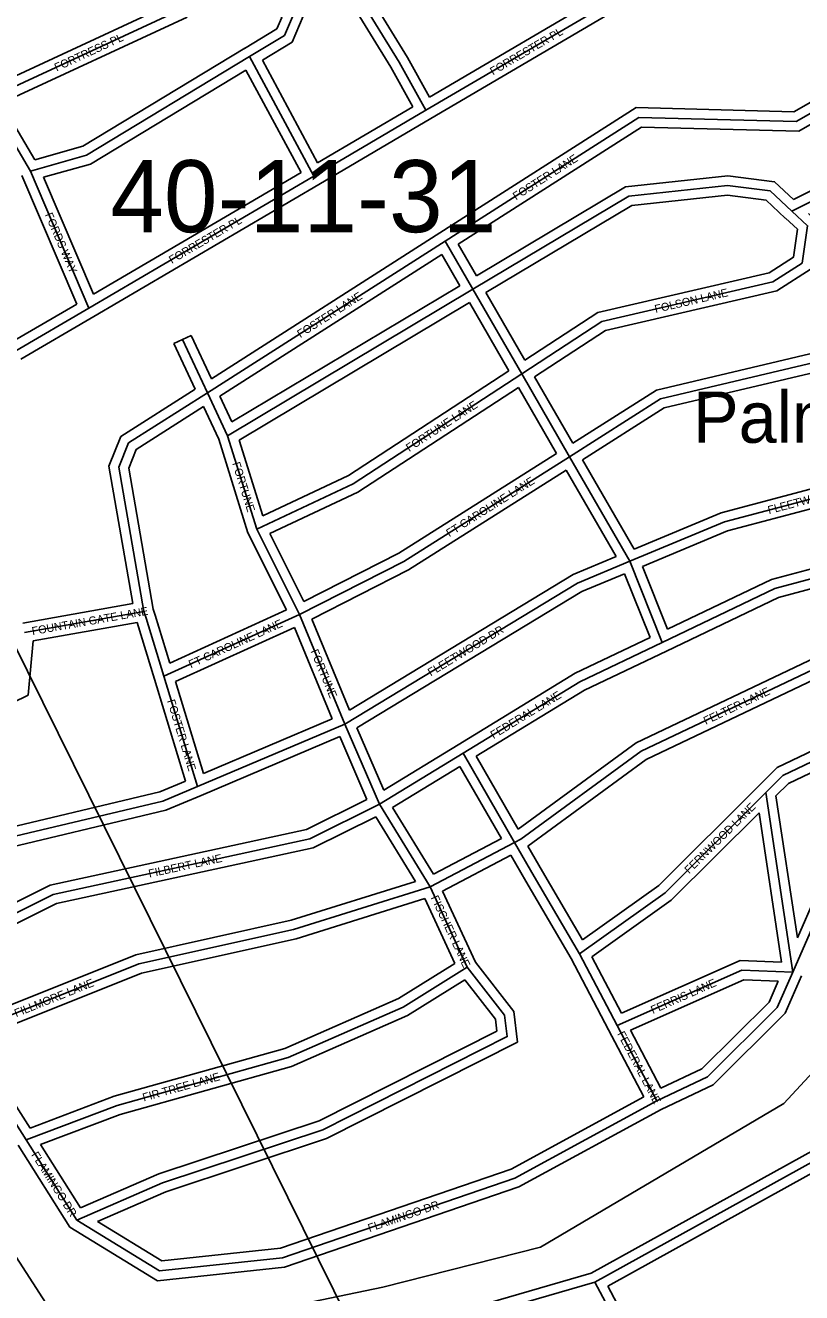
# Model space of a CAD drawing. Extents: x 457167 to 656239, y 1787309 to 1969297.
# Drawn here: x 586280 to 588703, y 1900964 to 1904923 of the extents above; entities that cross this region are included whole.
import ezdxf

# ---------------------------------------------------------------- set-up
doc = ezdxf.new("R2010")
doc.units = 0
for name, color, linetype in [('Level 1', 7, 'Continuous'), ('Level 2', 7, 'Continuous'), ('Level 31', 7, 'Continuous'), ('Level 32', 7, 'Continuous'), ('Level 34', 7, 'Continuous'), ('Level 44', 7, 'Continuous'), ('Level 5', 7, 'Continuous')]:
    doc.layers.add(name, color=color, linetype=linetype)

msp = doc.modelspace()

# ---------------------------------------------------------------- linework, layer by layer
at = {"layer": 'Level 1'}
msp.add_line((585103.985, 1905297.891), (587876.128, 1899689.718), dxfattribs=at)
at = {"layer": 'Level 31'}
for p, q in [((587446.958, 1904807.623), (587031.137, 1905483.681)), ((586163.078, 1904692.94), (586772.06, 1904975.432)), ((586980.002, 1904825.586), (587180.536, 1904452.115)), ((587446.958, 1904807.623), (587529.969, 1904657.65)), ((586163.078, 1904692.94), (586295.853, 1904467.958)), ((587529.969, 1904657.65), (587180.536, 1904452.115)), ((586295.853, 1904467.958), (586478.478, 1904039.971)), ((588672.237, 1904342.815), (588961.153, 1904487.746)), ((587180.536, 1904452.115), (586478.478, 1904039.971)), ((586848.34, 1903775.636), (587589.934, 1904249.169)), ((587589.934, 1904249.169), (587676.76, 1904098.824)), ((587676.76, 1904098.824), (586911.354, 1903641.334)), ((587676.76, 1904098.824), (587829.185, 1903834.538)), ((586478.478, 1904039.971), (586250.29, 1903906.582)), ((586848.34, 1903775.636), (586770.129, 1903941.966)), ((587829.185, 1903834.538), (587978.125, 1903575.714)), ((586911.354, 1903641.334), (586848.34, 1903775.636)), ((587002.685, 1903349.522), (586911.354, 1903641.334)), ((587978.125, 1903575.714), (588166.999, 1903249.181)), ((587135.71, 1903082.726), (587002.685, 1903349.522)), ((588166.999, 1903249.181), (588267.949, 1902995.536)), ((586277.245, 1903026.519), (586649.96, 1903092.363)), ((586649.96, 1903092.363), (586656.598, 1903071.259)), ((587135.71, 1903082.726), (586711.893, 1902889.698)), ((587276.864, 1902740.64), (587135.71, 1903082.726)), ((586656.598, 1903071.259), (586711.893, 1902889.698)), ((586711.893, 1902889.698), (586816.796, 1902545.133)), ((586816.796, 1902545.133), (587276.864, 1902740.64)), ((587384.809, 1902490.253), (587276.864, 1902740.64)), ((587384.809, 1902490.253), (587646.431, 1902650.133)), ((587807.099, 1902370.559), (587646.431, 1902650.133)), ((588675.231, 1901966.051), (588590.73, 1902526.576)), ((587542.972, 1902231.774), (587384.809, 1902490.253)), ((587542.972, 1902231.774), (587807.099, 1902370.559)), ((587867.944, 1902264.627), (587807.099, 1902370.559)), ((588009.292, 1902022.545), (587867.944, 1902264.627)), ((587659.186, 1901981.374), (587542.972, 1902231.774)), ((588126.83, 1901799.054), (588009.292, 1902022.545)), ((588250.389, 1901563.551), (588126.83, 1901799.054)), ((586282.847, 1901441.76), (586074.903, 1901767.249)), ((586440.704, 1901191.276), (586282.847, 1901441.76)), ((588057.643, 1900996.989), (588866.949, 1901446.058)), ((588248.698, 1900638.088), (588057.643, 1900996.989))]:
    msp.add_line(p, q, dxfattribs=at)
for points in [[(586980.002, 1904825.586), (587088.527, 1904891.566), (587113.75, 1904950.065), (586855.793, 1905384.008)], [(588398.07, 1905138.6), (588370.938, 1905077.921), (588259.602, 1905037.761), (588133.353, 1905012.539), (587529.969, 1904657.65)], [(586295.853, 1904467.958), (586471.108, 1904517.446), (586980.002, 1904825.586)], [(587589.934, 1904249.169), (588194.334, 1904635.694), (588686.098, 1904622.793), (588852.212, 1904717.765)], [(588672.237, 1904342.815), (588604.957, 1904405.847), (588471.788, 1904422.456), (588163.048, 1904389.931), (587676.76, 1904098.824)], [(587829.185, 1903834.538), (588079.039, 1903998.08), (588613.024, 1904122.192), (588704.687, 1904180.571), (588721.429, 1904297.27), (588672.237, 1904342.815)], [(587978.125, 1903575.714), (588262.027, 1903755.921), (588820.826, 1903888.356), (588975.539, 1904005.531)], [(587002.685, 1903349.522), (587303.052, 1903490.782), (587829.185, 1903834.538)], [(586649.96, 1903092.363), (586571.963, 1903542.697), (586601.989, 1903618.642), (586848.34, 1903775.636)], [(587135.71, 1903082.726), (587460.923, 1903248.667), (587978.125, 1903575.714)], [(588166.999, 1903249.181), (588461.609, 1903372.277), (588961.918, 1903504.821), (589387.396, 1903570.961), (589412.132, 1903537.461)], [(588267.949, 1902995.536), (588619.547, 1903163.622), (589019.99, 1903271.258), (589428.592, 1903320.701)], [(587276.864, 1902740.64), (588002.834, 1903181.118), (588166.999, 1903249.181)], [(587807.099, 1902370.559), (587826.512, 1902381.07), (588202.155, 1902655.653), (588777.76, 1902929.876), (589094.52, 1902996.21), (589436.349, 1903037.411)], [(587646.431, 1902650.133), (588010.534, 1902872.736), (588267.949, 1902995.536)], [(588590.73, 1902526.576), (588643.919, 1902579.933), (589027.655, 1902762.874), (589452.959, 1902903.924)], [(588675.231, 1901966.051), (588885.293, 1902446.401), (589102.381, 1902595.827), (589486.069, 1902753.681), (589452.959, 1902903.924)], [(585333.209, 1901943.573), (586150.745, 1902367.113), (586709.574, 1902499.879), (586816.796, 1902545.133)], [(588009.292, 1902022.545), (588276.376, 1902213.693), (588590.73, 1902526.576)], [(585941.738, 1901959.141), (586133.695, 1902092.233), (586367.267, 1902208.519), (587167.79, 1902382.293), (587384.809, 1902490.253)], [(586074.903, 1901767.249), (586633.912, 1901991.287), (587117.351, 1902099.11), (587542.972, 1902231.774)], [(586282.847, 1901441.76), (586566.32, 1901549.591), (587100.074, 1901698.773), (587458.983, 1901856.652), (587659.186, 1901981.374)], [(586440.704, 1901191.276), (586707.662, 1901307.503), (587208.069, 1901473.478), (587783.729, 1901764.412), (587775.586, 1901830.974), (587659.186, 1901981.374)], [(588126.83, 1901799.054), (588516.281, 1901971.432), (588675.231, 1901966.051)], [(588250.389, 1901563.551), (588408.852, 1901638.534), (588626.069, 1901854.866), (588675.231, 1901966.051)], [(586440.704, 1901191.276), (586698.883, 1901032.608), (587082.38, 1901073.707), (587808.032, 1901322.545), (588250.389, 1901563.551)], [(586772.736, 1900232.095), (586689.416, 1900390.799), (586714.766, 1900515.844), (586773.421, 1900599.007), (586998.369, 1900690.223), (588057.643, 1900996.989)]]:
    msp.add_lwpolyline(points, dxfattribs=at)
at = {"layer": 'Level 32'}
for p, q in [((587472.873, 1904822.754), (587056.524, 1905499.671)), ((587421.044, 1904792.491), (587020.767, 1905443.276)), ((586176.521, 1904732.246), (586759.436, 1905002.647)), ((586205.749, 1904679.661), (586784.684, 1904948.216)), ((587472.873, 1904822.753), (587541.304, 1904699.121)), ((586968.517, 1904783.558), (587140.444, 1904463.366)), ((587019.887, 1904814.723), (587192.212, 1904493.788)), ((587421.044, 1904792.492), (587489.569, 1904668.691)), ((586205.749, 1904679.661), (586309.944, 1904503.11)), ((587489.569, 1904668.691), (587192.212, 1904493.787)), ((587545.18, 1904631.79), (587195.746, 1904426.256)), ((588677.484, 1904379.009), (588921.486, 1904501.41)), ((586269.026, 1904454.39), (586440.505, 1904052.523)), ((586336.835, 1904448.356), (586492.692, 1904083.103)), ((587140.444, 1904463.366), (586492.691, 1904083.103)), ((587195.724, 1904426.243), (586493.667, 1904014.1)), ((586860.964, 1903819.291), (587573.788, 1904274.455)), ((587630.253, 1904239.341), (587687.499, 1904140.217)), ((586886.691, 1903764.528), (587579.643, 1904207.001)), ((587579.643, 1904207.001), (587636.003, 1904109.412)), ((587636.002, 1904109.412), (586924.427, 1903684.099)), ((587717.496, 1904088.242), (587839.316, 1903877.023)), ((586440.504, 1904052.523), (586235.15, 1903932.482)), ((587665.998, 1904057.438), (586947.05, 1903627.718)), ((587665.998, 1904057.438), (587789.02, 1903844.131)), ((586493.619, 1904014.071), (586265.43, 1903880.681)), ((586742.98, 1903929.201), (586797.279, 1903954.732)), ((586860.965, 1903819.291), (586797.279, 1903954.732)), ((586809.963, 1903786.752), (586742.98, 1903929.201)), ((587819.019, 1903792.056), (587937.771, 1903585.691)), ((587869.317, 1903824.949), (587988.5, 1903617.833)), ((586924.428, 1903684.1), (586886.691, 1903764.529)), ((586883.33, 1903630.431), (586835.68, 1903731.991)), ((586974.77, 1903338.277), (586883.33, 1903630.431)), ((587021.043, 1903391.308), (586947.05, 1903627.718)), ((588018.51, 1903565.812), (588179.766, 1903287.027)), ((587967.783, 1903533.678), (588123.894, 1903263.786)), ((587094.997, 1903097.147), (586974.77, 1903338.277)), ((587149.048, 1903123.211), (587043.232, 1903335.437)), ((588150.38, 1903209.811), (588229.695, 1903010.525)), ((588205.781, 1903232.87), (588283.959, 1903036.441)), ((586272.027, 1903056.061), (586615.298, 1903116.704)), ((586679.18, 1903099.453), (586685.216, 1903080.259)), ((586685.216, 1903080.259), (586730.617, 1902931.191)), ((587094.997, 1903097.147), (586730.617, 1902931.191)), ((586304.892, 1903000.936), (586629.207, 1903058.231)), ((586629.207, 1903058.231), (586683.194, 1902880.958)), ((587119.843, 1903042.531), (586748.249, 1902873.29)), ((587237.809, 1902756.639), (587119.843, 1903042.531)), ((587291.241, 1902784.452), (587174.001, 1903068.581)), ((586288.293, 1902830.921), (586304.892, 1903000.936)), ((586683.193, 1902880.961), (586780.223, 1902562.259)), ((586748.249, 1902873.29), (586835.778, 1902585.795)), ((585522.224, 1902458.086), (586288.293, 1902830.921)), ((586835.777, 1902585.795), (587237.809, 1902756.639)), ((587398.669, 1902533.881), (587314.753, 1902728.535)), ((586828.53, 1902517.521), (587261.132, 1902701.355)), ((587346.015, 1902504.461), (587261.132, 1902701.355)), ((587398.67, 1902533.881), (587630.788, 1902675.732)), ((587426.068, 1902480.306), (587635.777, 1902608.462)), ((587765.565, 1902382.623), (587635.778, 1902608.462)), ((587817.915, 1902411.947), (587686.99, 1902639.766)), ((588689.399, 1902073.323), (588622.649, 1902516.1)), ((587497.287, 1902248.958), (587373.565, 1902451.151)), ((587553.894, 1902271.403), (587426.068, 1902480.306)), ((588640.189, 1901997.254), (588569.899, 1902463.512)), ((587553.894, 1902271.403), (587765.565, 1902382.623)), ((587582.208, 1902218.499), (587795.477, 1902330.561)), ((587841.93, 1902249.685), (587795.476, 1902330.561)), ((587893.853, 1902279.754), (587847.989, 1902359.606)), ((587983.049, 1902007.991), (587842.038, 1902249.501)), ((588018.601, 1902066.099), (587893.853, 1902279.754)), ((587684.978, 1901997.066), (587582.208, 1902218.499)), ((587620.805, 1901992.808), (587526.819, 1902195.314)), ((588140.331, 1901837.836), (588048.016, 1902013.365)), ((588100.279, 1901785.089), (587983.049, 1902007.991)), ((588210.103, 1901575.765), (588100.265, 1901785.115)), ((588263.581, 1901602.981), (588168.294, 1901784.596)), ((586294.991, 1901478.476), (586119.686, 1901752.876)), ((588046.048, 1901024.863), (588844.303, 1901467.8)), ((586419.048, 1901169.373), (586257.566, 1901425.607)), ((586452.349, 1901229.066), (586327.769, 1901426.748)), ((588097.979, 1900985.061), (588862.844, 1901409.47)), ((588273.664, 1900655.033), (588097.98, 1900985.061))]:
    msp.add_line(p, q, dxfattribs=at)
for points in [[(586964.418, 1904851.221), (587064.766, 1904912.23), (587080.142, 1904947.891), (586845.121, 1905343.251)], [(587019.887, 1904814.722), (587112.288, 1904870.901), (587147.358, 1904952.24), (586897.213, 1905373.043)], [(588370.603, 1905150.666), (588348.759, 1905101.813), (588251.529, 1905066.742), (588122.509, 1905040.966), (587541.304, 1904699.121)], [(588415.925, 1905105.033), (588393.118, 1905054.029), (588267.675, 1905008.781), (588144.196, 1904984.111), (587545.179, 1904631.79)], [(586309.944, 1904503.111), (586459.045, 1904545.214), (586964.464, 1904851.249)], [(586336.835, 1904448.356), (586483.171, 1904489.679), (586968.518, 1904783.559)], [(587573.77, 1904274.444), (588185.923, 1904665.926), (588678.494, 1904653.004), (588837.321, 1904743.809)], [(587630.253, 1904239.342), (588202.746, 1904605.462), (588693.702, 1904592.582), (588838.971, 1904675.635)], [(588677.484, 1904379.009), (588618.349, 1904434.411), (588472.075, 1904452.653), (588153.32, 1904419.073), (587687.499, 1904140.217)], [(588651.726, 1904320.921), (588591.564, 1904377.284), (588471.499, 1904392.258), (588172.776, 1904360.788), (587717.496, 1904088.243)], [(587839.315, 1903877.023), (588067.064, 1904026.096), (588601.235, 1904150.253), (588676.948, 1904198.473), (588689.498, 1904285.949), (588651.855, 1904320.801)], [(587869.317, 1903824.949), (588091.016, 1903970.063), (588624.814, 1904094.131), (588732.425, 1904162.67), (588753.361, 1904308.59), (588724.39, 1904335.412)], [(587988.5, 1903617.833), (588250.205, 1903783.951), (588807.755, 1903916.09), (588957.427, 1904029.446)], [(588018.51, 1903565.812), (588273.849, 1903727.891), (588833.898, 1903860.622), (588972.665, 1903965.718)], [(587021.043, 1903391.308), (587288.394, 1903517.041), (587789.02, 1903844.131)], [(587043.232, 1903335.436), (587317.711, 1903464.524), (587819.019, 1903792.057)], [(586615.299, 1903116.703), (586540.963, 1903545.886), (586577.664, 1903638.716), (586809.963, 1903786.752)], [(586679.18, 1903099.454), (586602.962, 1903539.508), (586626.313, 1903598.568), (586835.68, 1903731.991)], [(588179.766, 1903287.028), (588451.939, 1903400.751), (588955.755, 1903534.225), (589400.739, 1903603.396), (589425.693, 1903569.601)], [(587149.049, 1903123.21), (587446.056, 1903274.762), (587937.772, 1903585.691)], [(587174, 1903068.581), (587475.789, 1903222.573), (587967.782, 1903533.677)], [(588205.781, 1903232.869), (588471.278, 1903343.803), (588968.079, 1903475.418), (589374.054, 1903538.526), (589382.873, 1903526.582)], [(588283.959, 1903036.441), (588609.095, 1903191.879), (589014.266, 1903300.785), (589396.506, 1903347.037)], [(588280.889, 1902968.47), (588629.998, 1903135.366), (589025.715, 1903241.731), (589399.505, 1903286.961)], [(587291.241, 1902784.452), (587989.229, 1903207.954), (588123.894, 1903263.786)], [(587314.753, 1902728.535), (588016.439, 1903154.281), (588150.38, 1903209.812)], [(587817.915, 1902411.947), (588186.719, 1902681.531), (588768.099, 1902958.504), (589089.642, 1903025.84), (589405.613, 1903063.922)], [(587630.782, 1902675.73), (587996.212, 1902899.144), (588229.694, 1903010.526)], [(587847.989, 1902359.606), (588217.593, 1902629.776), (588787.423, 1902901.248), (589099.399, 1902966.58), (589410.269, 1903004.047)], [(587686.99, 1902639.766), (588024.854, 1902846.327), (588280.867, 1902968.459)], [(588569.566, 1902547.84), (588626.331, 1902604.784), (589016.434, 1902790.761), (589420.15, 1902924.648)], [(588622.649, 1902516.101), (588661.507, 1902555.083), (589038.876, 1902734.987), (589430.823, 1902864.975)], [(588689.4, 1902073.322), (588861.234, 1902466.262), (589088.007, 1902622.354), (589451.349, 1902771.836), (589430.824, 1902864.973)], [(585320.235, 1901970.639), (586140.221, 1902395.448), (586700.209, 1902528.49), (586780.222, 1902562.259)], [(588018.601, 1902066.1), (588256.937, 1902236.673), (588569.566, 1902547.84)], [(585377.014, 1901932.478), (586161.269, 1902338.777), (586718.939, 1902471.268), (586828.462, 1902517.493)], [(585924.091, 1901983.409), (586118.384, 1902118.122), (586357.246, 1902237.043), (587157.774, 1902410.817), (587346.014, 1902504.461)], [(585983.497, 1901951.586), (586149.008, 1902066.343), (586377.289, 1902179.996), (587177.807, 1902353.768), (587373.565, 1902451.15)], [(588048.016, 1902013.366), (588295.815, 1902190.712), (588569.898, 1902463.513)], [(586085.924, 1901803.986), (586625.008, 1902020.04), (587109.609, 1902128.121), (587497.287, 1902248.958)], [(586119.686, 1901752.876), (586642.816, 1901962.535), (587125.094, 1902070.099), (587526.819, 1902195.314)], [(586294.99, 1901478.476), (586556.929, 1901578.116), (587089.946, 1901727.093), (587444.94, 1901883.251), (587620.805, 1901992.808)], [(586505.408, 1901186.726), (586718.394, 1901279.456), (587219.619, 1901445.702), (587816.067, 1901747.141), (587804.362, 1901842.81), (587684.978, 1901997.066)], [(588140.331, 1901837.836), (588510.424, 1902001.649), (588640.189, 1901997.254)], [(586327.769, 1901426.749), (586575.711, 1901521.065), (587110.204, 1901670.453), (587473.026, 1901830.054), (587652.049, 1901941.581)], [(586452.349, 1901229.067), (586696.93, 1901335.551), (587196.517, 1901501.255), (587751.392, 1901781.685), (587746.81, 1901819.139), (587652.049, 1901941.58)], [(588168.294, 1901784.596), (588522.137, 1901941.216), (588629.836, 1901937.569)], [(588263.581, 1901602.981), (588391.346, 1901663.44), (588600.909, 1901872.149), (588629.837, 1901937.569)], [(588263.994, 1901536.797), (588426.359, 1901613.627), (588651.23, 1901837.583), (588702.669, 1901953.918)], [(586505.408, 1901186.725), (586705.866, 1901063.528), (587075.835, 1901103.178), (587795.904, 1901350.101), (588210.103, 1901575.764)], [(586419.048, 1901169.373), (586691.899, 1901001.687), (587088.926, 1901044.236), (587820.159, 1901294.988), (588263.994, 1901536.797)], [(586746.845, 1900216.871), (586657.893, 1900386.302), (586686.617, 1900527.983), (586753.983, 1900623.499), (586988.534, 1900718.608), (588046.048, 1901024.864)]]:
    msp.add_lwpolyline(points, dxfattribs=at)
at = {"layer": 'Level 5'}
msp.add_lwpolyline([(586678.859, 1900832.42), (587395.936, 1900981.716), (587887.911, 1901106.242), (588646.995, 1901555.587), (588855.624, 1901780.444), (589072.92, 1902297.067), (589156.38, 1902372), (589348.212, 1902455.162), (589683.334, 1902486.413)], dxfattribs=at)
msp.add_lwpolyline([(586353.833, 1900916.14), (586095.251, 1900766.345), (585995.18, 1900741.464), (585604.056, 1901367.086), (585946.039, 1901550.123), (586087.563, 1901374.93), (586137.455, 1901249.816), (586353.833, 1900916.14)], close=True, dxfattribs=at)

# ---------------------------------------------------------------- texts
at = {"layer": 'Level 2'}
msp.add_text('40-11-31', height=225, dxfattribs=at).set_placement((586545.224, 1904276.936))
at = {"layer": 'Level 34'}
for s, height, rotation, p in [('FORRESTER PL', 25, 30.461922, (587739.449, 1904766.358)), ('FORTRESS PL', 25, 24.884819, (586377.684, 1904778.713)), ('FOSTER LANE', 25, 32.598958, (587811.305, 1904375.904)), ('FORDS WAY', 25, 293.107739, (586340.439, 1904331.621)), ('FORRESTER PL', 25, 30.414383, (586737.238, 1904177.383)), ('FOSTER LANE', 25, 32.558933, (587138.262, 1903945.931)), ('FOLSON LANE', 24.99916, 13.084375, (588247.168, 1904024.325)), ('FORTUNE LANE', 25, 33.158381, (587478.034, 1903590.179)), ('FORTUNE', 25, 287.378575, (586925.334, 1903554.817)), ('FT CAROLINE LANE', 25, 32.306, (587603.217, 1903323.858)), ('FLEETWOOD DR', 25, 14.837639, (588600.792, 1903396.221)), ('FOUNTAIN GATE LANE', 25, 10.018064, (586302.479, 1903018.285)), ('FT CAROLINE LANE', 25, 24.486186, (586796.558, 1902914.525)), ('FLEETWOOD DR', 25, 31.246392, (587545.355, 1902888.926)), ('FORTUNE', 25, 292.421856, (587169.504, 1902968.056)), ('FEDERAL LANE', 25, 31.439822, (587741.085, 1902693.352)), ('FELTER LANE', 25, 25.4729, (588403.634, 1902737.794)), ('FOSTER LANE', 25, 286.932422, (586722.114, 1902813.206)), ('FERNWOOD LANE', 25, 44.864736, (588351.961, 1902271.29)), ('FILBERT LANE', 25, 12.246958, (586667.224, 1902260.841)), ('FISCHER LANE', 25, 294.896178, (587544.793, 1902198.161)), ('FILLMORE LANE', 25, 21.839267, (586251.616, 1901824.606)), ('FERRIS LANE', 25, 23.874564, (588238.484, 1901834.804)), ('FEDERAL LANE', 25, 297.683794, (588126.399, 1901772.972)), ('FIR TREE LANE', 25, 15.615072, (586649.839, 1901561.637)), ('FLAMINGO DR', 25, 302.219114, (586297.549, 1901394.989)), ('FLAMINGO DR', 25, 18.927056, (587354.072, 1901153.661))]:
    msp.add_text(s, height=height, rotation=rotation, dxfattribs=at).set_placement(p)
at = {"layer": 'Level 44'}
msp.add_text('Palm Coast', height=160, dxfattribs=at).set_placement((588363.425, 1903619.156))

doc.saveas('drawing.dxf')
